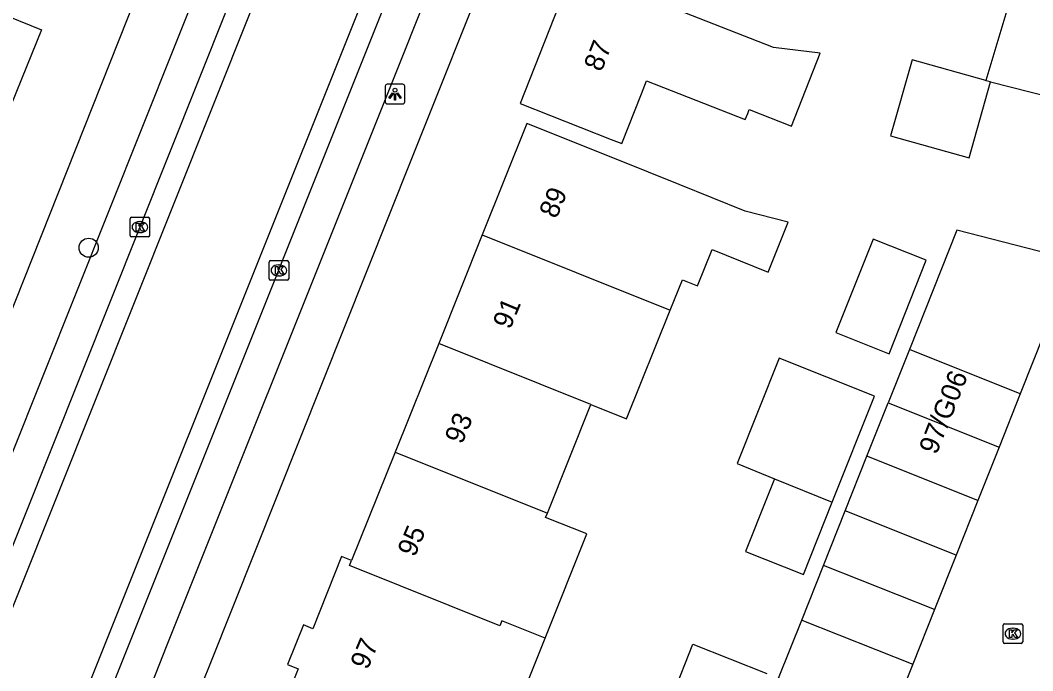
# Model space of a CAD drawing. Extents: x 160026 to 161302, y 384757 to 385701.
# Drawn here: x 160406.9 to 160458.6, y 384951.2 to 384984.4 of the extents above; entities that cross this region are included whole.
import ezdxf

# ---------------------------------------------------------------- set-up
doc = ezdxf.new("R2010")
doc.units = 0
for name, color, linetype in [('IMGEO_Boom', 7, 'Continuous'), ('IMGEO_Kolk', 7, 'Continuous'), ('IMGEO_Lichtpunt', 7, 'Continuous'), ('IMGEO_Pand', 7, 'Continuous'), ('IMGEO_Pand_nummerreeks', 7, 'Continuous'), ('IMGEO_Rijbaan_lokaal_open', 7, 'Continuous'), ('IMGEO_Voetpad_open', 7, 'Continuous')]:
    doc.layers.add(name, color=color, linetype=linetype)

msp = doc.modelspace()

# ---------------------------------------------------------------- linework, layer by layer
at = {"layer": 'IMGEO_Boom'}
msp.add_circle((160410.437, 384972.767), 0.489, dxfattribs=at)
at = {"layer": 'IMGEO_Kolk'}
for p, q in [((160412.546, 384973.394), (160412.546, 384974.246)), ((160412.621, 384974.32), (160413.473, 384974.32)), ((160413.547, 384974.246), (160413.547, 384973.394)), ((160413.034, 384974.1), (160413.059, 384974.1)), ((160413.473, 384973.32), (160412.621, 384973.32)), ((160413.057, 384973.54), (160413.032, 384973.54)), ((160419.714, 384972.109), (160420.566, 384972.109)), ((160419.639, 384971.183), (160419.639, 384972.035)), ((160420.127, 384971.889), (160420.152, 384971.889)), ((160420.64, 384972.035), (160420.64, 384971.183)), ((160420.566, 384971.109), (160419.714, 384971.109)), ((160420.15, 384971.329), (160420.125, 384971.329)), ((160457.086, 384952.634), (160457.086, 384953.486)), ((160457.161, 384953.56), (160458.013, 384953.56)), ((160458.087, 384953.486), (160458.087, 384952.634)), ((160457.574, 384953.34), (160457.599, 384953.34)), ((160458.013, 384952.56), (160457.161, 384952.56)), ((160457.597, 384952.78), (160457.572, 384952.78))]:
    msp.add_line(p, q, dxfattribs=at)
for points in [[(160412.546, 384973.394), (160412.546, 384974.246)], [(160412.621, 384974.32), (160413.473, 384974.32)], [(160413.547, 384974.246), (160413.547, 384973.394)], [(160412.867, 384974.02), (160412.99, 384974.02), (160412.99, 384973.869), (160413.12, 384974.02), (160413.284, 384974.02), (160413.138, 384973.869), (160413.291, 384973.62), (160413.139, 384973.62), (160413.054, 384973.784), (160412.99, 384973.717), (160412.99, 384973.62), (160412.867, 384973.62), (160412.867, 384974.02)], [(160413.473, 384973.32), (160412.621, 384973.32)], [(160419.714, 384972.109), (160420.566, 384972.109)], [(160419.639, 384971.183), (160419.639, 384972.035)], [(160419.96, 384971.809), (160420.083, 384971.809), (160420.083, 384971.658), (160420.213, 384971.809), (160420.377, 384971.809), (160420.231, 384971.658), (160420.384, 384971.409), (160420.232, 384971.409), (160420.147, 384971.573), (160420.083, 384971.506), (160420.083, 384971.409), (160419.96, 384971.409), (160419.96, 384971.809)], [(160420.64, 384972.035), (160420.64, 384971.183)], [(160420.566, 384971.109), (160419.714, 384971.109)], [(160457.086, 384952.634), (160457.086, 384953.486)], [(160457.161, 384953.56), (160458.013, 384953.56)], [(160458.087, 384953.486), (160458.087, 384952.634)], [(160457.407, 384953.26), (160457.53, 384953.26), (160457.53, 384953.109), (160457.66, 384953.26), (160457.824, 384953.26), (160457.678, 384953.109), (160457.831, 384952.86), (160457.679, 384952.86), (160457.594, 384953.024), (160457.53, 384952.957), (160457.53, 384952.86), (160457.407, 384952.86), (160457.407, 384953.26)], [(160458.013, 384952.56), (160457.161, 384952.56)]]:
    msp.add_lwpolyline(points, dxfattribs=at)
for centre, start, end in [((160412.623, 384974.244), 91.552, 178.448), ((160412.623, 384974.244), 91.552, 178.448), ((160413.471, 384974.244), 1.552, 88.448), ((160413.471, 384974.244), 1.552, 88.448), ((160412.623, 384973.396), 181.552, 268.448), ((160412.623, 384973.396), 181.552, 268.448), ((160413.471, 384973.396), 271.552, 358.448), ((160413.471, 384973.396), 271.552, 358.448), ((160419.716, 384972.033), 91.552, 178.448), ((160419.716, 384972.033), 91.552, 178.448), ((160420.564, 384972.033), 1.552, 88.448), ((160420.564, 384972.033), 1.552, 88.448), ((160419.716, 384971.185), 181.552, 268.448), ((160419.716, 384971.185), 181.552, 268.448), ((160420.564, 384971.185), 271.552, 358.448), ((160420.564, 384971.185), 271.552, 358.448), ((160457.163, 384953.484), 91.552, 178.448), ((160457.163, 384953.484), 91.552, 178.448), ((160458.011, 384953.484), 1.552, 88.448), ((160458.011, 384953.484), 1.552, 88.448), ((160457.163, 384952.636), 181.552, 268.448), ((160457.163, 384952.636), 181.552, 268.448), ((160458.011, 384952.636), 271.552, 358.448), ((160458.011, 384952.636), 271.552, 358.448)]:
    msp.add_arc(centre, 0.0765, start, end, dxfattribs=at)
for centre, major_axis, ratio, start_param, end_param in [((160413.033, 384973.82), (-0.387, 0.002), 0.722429, 4.712389, 7.853982), ((160413.058, 384973.82), (-0.39, 0.002), 0.717154, 1.570796, 4.712389), ((160420.126, 384971.609), (-0.387, 0.002), 0.722429, 4.712389, 7.853982), ((160420.151, 384971.609), (-0.39, 0.002), 0.717154, 1.570796, 4.712389), ((160457.573, 384953.06), (-0.387, 0.002), 0.722429, 4.712389, 7.853982), ((160457.598, 384953.06), (-0.39, 0.002), 0.717154, 1.570796, 4.712389)]:
    msp.add_ellipse(centre, major_axis=major_axis, ratio=ratio, start_param=start_param, end_param=end_param, dxfattribs=at)
at = {"layer": 'IMGEO_Lichtpunt'}
for p, q in [((160425.567, 384981.016), (160425.567, 384980.209)), ((160425.567, 384981.016), (160425.567, 384980.209)), ((160426.469, 384981.111), (160425.661, 384981.111)), ((160426.469, 384981.111), (160425.661, 384981.111)), ((160426.563, 384980.209), (160426.563, 384981.016)), ((160426.563, 384980.209), (160426.563, 384981.016)), ((160425.661, 384980.115), (160426.469, 384980.115)), ((160425.661, 384980.115), (160426.469, 384980.115))]:
    msp.add_line(p, q, dxfattribs=at)
for points in [[(160425.941, 384980.68), (160425.98, 384980.652), (160425.792, 384980.39), (160425.754, 384980.417), (160425.941, 384980.68)], [(160426.043, 384980.632), (160426.09, 384980.632), (160426.09, 384980.31), (160426.043, 384980.31), (160426.043, 384980.632)], [(160426.153, 384980.652), (160426.191, 384980.679), (160426.378, 384980.417), (160426.339, 384980.389), (160426.153, 384980.652)]]:
    msp.add_lwpolyline(points, dxfattribs=at)
msp.add_circle((160426.066, 384980.814), 0.0994, dxfattribs=at)
for centre, start, end in [((160425.661, 384981.016), 90, 180), ((160425.661, 384981.016), 90, 180), ((160426.469, 384981.016), 0, 90), ((160426.469, 384981.016), 0, 90), ((160425.661, 384980.209), 180, 270), ((160425.661, 384980.209), 180, 270), ((160426.469, 384980.209), 270, 0), ((160426.469, 384980.209), 270, 360)]:
    msp.add_arc(centre, 0.0946, start, end, dxfattribs=at)
at = {"layer": 'IMGEO_Pand'}
for points in [[(160459.049, 384990.235), (160459.029, 384990.166), (160458.861, 384990.214), (160457.635, 384986.088), (160456.213, 384981.301)], [(160399.047, 384983.902), (160400.321, 384987.047), (160403.4, 384985.788), (160408.027, 384983.896), (160405.676, 384978.145), (160401.035, 384980.005), (160397.969, 384981.242), (160392.75, 384983.348), (160393.832, 384986.016), (160399.047, 384983.902)], [(160437.635, 384978.085), (160438.632, 384980.617), (160438.897, 384981.29), (160443.935, 384979.307), (160444.059, 384979.623), (160444.136, 384979.818), (160446.285, 384978.972), (160447.751, 384982.697), (160445.383, 384982.986), (160435.157, 384987.011), (160432.447, 384980.127), (160437.1, 384978.296), (160437.635, 384978.085)], [(160456.213, 384981.301), (160452.446, 384982.364), (160451.352, 384978.487), (160455.352, 384977.358), (160456.446, 384981.235)], [(160456.446, 384981.235), (160456.211, 384981.295), (160456.213, 384981.301)], [(160456.446, 384981.235), (160472.11, 384977.254)], [(160440.11, 384969.581), (160440.73, 384971.126), (160441.5, 384970.815), (160442.249, 384972.682), (160445.108, 384971.526), (160446.127, 384974.067), (160443.926, 384974.64), (160440.566, 384976), (160437.439, 384977.254), (160432.798, 384979.114), (160430.518, 384973.428)], [(160460.376, 384971.378), (160460.672, 384972.123), (160454.73, 384973.66), (160452.307, 384967.562)], [(160430.518, 384973.428), (160428.294, 384967.882)], [(160430.518, 384973.428), (160440.11, 384969.581)], [(160448.557, 384968.432), (160451.269, 384967.353), (160453.169, 384972.129), (160450.456, 384973.208), (160448.557, 384968.432)], [(160460.376, 384971.378), (160457.966, 384965.313)], [(160436.06, 384964.762), (160437.882, 384964.025), (160440.11, 384969.581)], [(160428.294, 384967.882), (160426.07, 384962.335)], [(160436.06, 384964.762), (160428.294, 384967.882)], [(160452.307, 384967.562), (160451.224, 384964.839)], [(160457.966, 384965.313), (160452.307, 384967.562)], [(160448.37, 384959.769), (160450.525, 384965.193), (160445.656, 384967.128), (160443.515, 384961.74), (160445.423, 384960.965)], [(160450.141, 384962.114), (160451.224, 384964.839)], [(160451.224, 384964.839), (160456.883, 384962.59)], [(160457.966, 384965.313), (160456.883, 384962.59)], [(160433.837, 384959.219), (160436.06, 384964.762)], [(160426.07, 384962.335), (160423.845, 384956.791)], [(160426.07, 384962.335), (160433.837, 384959.219)], [(160456.883, 384962.59), (160455.8, 384959.865)], [(160449.032, 384959.325), (160450.141, 384962.114)], [(160455.8, 384959.865), (160450.141, 384962.114)], [(160445.423, 384960.965), (160445.05, 384960.029), (160443.946, 384957.249), (160446.901, 384956.074), (160448.37, 384959.769)], [(160445.423, 384960.965), (160448.37, 384959.769)], [(160455.8, 384959.865), (160454.691, 384957.075)], [(160433.72, 384952.825), (160435.856, 384958.153), (160433.748, 384958.998), (160433.837, 384959.219)], [(160447.923, 384956.534), (160449.032, 384959.325)], [(160454.691, 384957.075), (160449.032, 384959.325)], [(160454.691, 384957.075), (160453.582, 384954.285)], [(160423.845, 384956.791), (160423.34, 384956.993), (160421.864, 384953.313), (160421.394, 384953.502), (160420.582, 384951.477), (160421.129, 384951.258), (160420.753, 384950.32), (160423.213, 384949.334), (160432.481, 384945.618), (160432.582, 384945.577), (160435.502, 384944.407), (160436.826, 384944.822), (160437.65, 384946.942), (160437.039, 384948.242), (160434.018, 384949.453), (160432.596, 384950.023), (160433.72, 384952.825)], [(160433.72, 384952.825), (160431.518, 384953.709), (160431.415, 384953.452), (160423.741, 384956.532), (160423.845, 384956.791)], [(160446.817, 384953.749), (160447.923, 384956.534)], [(160453.582, 384954.285), (160447.923, 384956.534)], [(160453.582, 384954.285), (160452.476, 384951.501)], [(160445.638, 384950.784), (160446.817, 384953.749)], [(160446.817, 384953.749), (160452.476, 384951.501)], [(160440.25, 384949.977), (160441.262, 384952.523), (160445.036, 384951.023)], [(160452.476, 384951.501), (160451.298, 384948.538), (160445.638, 384950.784)]]:
    msp.add_lwpolyline(points, dxfattribs=at)
at = {"layer": 'IMGEO_Rijbaan_lokaal_open'}
for points in [[(160387.693, 384910.244), (160423.495, 385000), (160443.146, 385049.264)], [(160385.418, 384898), (160385.618, 384898.566), (160388.819, 384909.958), (160424.752, 385000), (160444.248, 385048.841)], [(160448.949, 385047.038), (160436.681, 385016.096), (160430.241, 385000), (160388.913, 384896.667)], [(160382.619, 384876.93), (160386.339, 384887.1), (160431.47, 385000), (160434.346, 385007.194)]]:
    msp.add_lwpolyline(points, dxfattribs=at)
at = {"layer": 'IMGEO_Voetpad_open'}
for points in [[(160441.621, 385050.24), (160421.572, 385000), (160394.613, 384932.443)], [(160386.007, 384917.894), (160418.576, 385000), (160436.61, 385045.463)], [(160428.955, 384988.826), (160424.716, 384978.214), (160414.395, 384952.383), (160413.481, 384950.096)], [(160416.272, 384950.612), (160416.629, 384951.506), (160426.923, 384977.317), (160431.128, 384987.859)]]:
    msp.add_lwpolyline(points, dxfattribs=at)

# ---------------------------------------------------------------- texts
at = {"layer": 'IMGEO_Pand_nummerreeks'}
for s, rotation, p in [('87', 68.5143, (160436.594, 384981.707)), ('89', 67.2996, (160434.301, 384974.206)), ('91', 67.2996, (160431.936, 384968.553)), ('97/G06', 68.3477, (160453.689, 384962.157)), ('93', 67.2996, (160429.483, 384962.689)), ('95', 67.2996, (160427.074, 384956.93)), ('97', 67.2996, (160424.665, 384951.17))]:
    msp.add_text(s, height=1, rotation=rotation, dxfattribs=at).set_placement(p)

doc.saveas('drawing.dxf')
